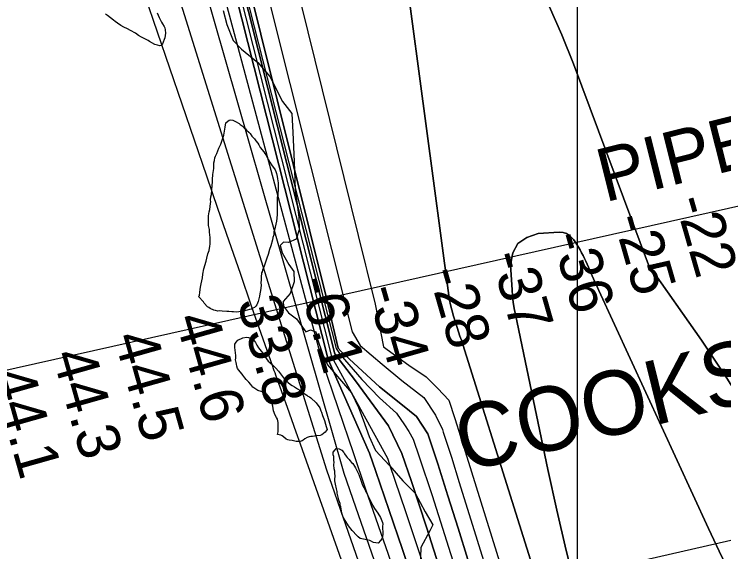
# Model space of a CAD drawing. Extents: x 3250478 to 3288318, y 788638 to 816472.
# Drawn here: x 3274716 to 3275823, y 796576 to 797415 of the extents above; entities that cross this region are included whole.
import ezdxf

# ---------------------------------------------------------------- set-up
doc = ezdxf.new("R2010")
doc.units = 0
for name, color, linetype in [('V-GRID-MAJR', 7, 'Continuous'), ('V-RIVR-EDGE', 7, 'Continuous'), ('V-RIVR-RANG', 7, 'Continuous'), ('V-SITE-VEGE', 7, 'Continuous'), ('V-TOPO-DPTH', 7, 'Continuous'), ('V-TOPO-GNAM-IDEN', 7, 'Continuous'), ('V-TOPO-MAJR', 7, 'Continuous'), ('V-TOPO-MINR', 7, 'Continuous'), ('V-TOPO-WATR', 7, 'Continuous'), ('V-UTIL-IDEN', 7, 'Continuous'), ('V-UTIL-LINE', 7, 'Continuous')]:
    doc.layers.add(name, color=color, linetype=linetype)

msp = doc.modelspace()

# ---------------------------------------------------------------- linework, layer by layer
at = {"layer": 'V-GRID-MAJR'}
msp.add_spline([(3275593.9, 794016.6), (3275594.8, 800075.6), (3275595.7, 806137.8), (3275596.6, 812200), (3275596.6, 812203)], degree=3, dxfattribs=at)
at = {"layer": 'V-RIVR-EDGE'}
msp.add_lwpolyline([(3275041.6, 797420.6), (3275047.7, 797398.4), (3275057.2, 797373.6), (3275070.6, 797360.1), (3275095.8, 797339.1), (3275114.8, 797317.4), (3275134.3, 797278.6), (3275149, 797259.5), (3275150.3, 797229.9), (3275152.3, 797184.7), (3275154, 797141.2), (3275159.9, 797097.7), (3275160.3, 797078.2), (3275155.5, 797063.8), (3275143.7, 797058.2), (3275135.9, 797058.7), (3275130.7, 797053.9), (3275133.7, 797042.2), (3275144.1, 797023.9), (3275151.9, 797013), (3275152.7, 796996.9), (3275146.2, 796978.7), (3275135.3, 796966.5), (3275136.1, 796959.1), (3275143.9, 796948.7), (3275156.1, 796939.1), (3275170.8, 796919.1), (3275177.8, 796922.1), (3275186.4, 796919), (3275187.7, 796910.8), (3275197.2, 796882.9), (3275204.6, 796867.7), (3275241.8, 796823.7), (3275252.7, 796801.1), (3275260, 796781.5), (3275269.5, 796755.4), (3275279.4, 796734), (3275301.1, 796710.5), (3275321.9, 796686.6), (3275341.4, 796667.4), (3275357, 796638.2), (3275368.7, 796617.8), (3275364.3, 796608.6), (3275350.3, 796582.2), (3275349, 796551.7)], dxfattribs=at)
at = {"layer": 'V-SITE-VEGE'}
for points in [[(3274938.9, 797416.7), (3274941.8, 797409.7), (3274943.5, 797406.4), (3274945.4, 797402.2), (3274947, 797399.8), (3274949.9, 797395.6), (3274950.9, 797393.2), (3274951.3, 797390.4), (3274951.8, 797384.9), (3274951.6, 797381.6), (3274950.8, 797377.9), (3274947.1, 797368.3), (3274945.3, 797365.8), (3274943.2, 797365.1), (3274939.2, 797366.2), (3274935.2, 797367.6), (3274926.8, 797372), (3274924.6, 797373.4), (3274914.3, 797378.9), (3274910, 797381.5), (3274905, 797384.8), (3274897.2, 797389.4), (3274892.8, 797391.7), (3274886.9, 797394.3), (3274882.3, 797396.9), (3274877, 797400.4), (3274873.5, 797403.1), (3274870.7, 797405.5), (3274861.6, 797412.8), (3274858.5, 797414.9)], [(3275011.2, 796965.7), (3275003.3, 796974), (3275005, 796975.9), (3275005.2, 796980.8), (3275006.5, 796988.5), (3275007.6, 796994), (3275009.4, 797003), (3275010.2, 797009.1), (3275011.8, 797017.1), (3275015.4, 797029.5), (3275016.5, 797033.8), (3275018.1, 797040.9), (3275019.8, 797045.8), (3275021.1, 797052.9), (3275021.6, 797055.7), (3275021.7, 797063), (3275021.6, 797066.7), (3275020.9, 797069.7), (3275020.4, 797074.9), (3275020.3, 797078.9), (3275019.2, 797085), (3275019.1, 797089.2), (3275018.9, 797096), (3275018.7, 797100.2), (3275019.8, 797106.4), (3275020.9, 797110.1), (3275022.2, 797119), (3275022.4, 797121.8), (3275022, 797124.8), (3275022.8, 797129.4), (3275023.6, 797133.4), (3275024.3, 797140.5), (3275025.1, 797153.4), (3275025, 797156.7), (3275025.7, 797164.4), (3275027.2, 797173.9), (3275027.1, 797178.2), (3275027.3, 797182.5), (3275028.1, 797186.5), (3275028.6, 797190.5), (3275029.7, 797193.3), (3275031.7, 797197.3), (3275035.2, 797205.4), (3275038, 797211.9), (3275043.1, 797226.1), (3275045.2, 797238.1), (3275046.2, 797245.2), (3275048.9, 797247.7), (3275051.3, 797249.3), (3275054, 797250), (3275056.8, 797249.5), (3275060.9, 797247.2), (3275066.8, 797244.3), (3275068.3, 797242.5), (3275071.2, 797240.4), (3275074.6, 797237.5), (3275076.5, 797236), (3275078.4, 797233.6), (3275081.6, 797230.3), (3275083.8, 797228.3), (3275086.6, 797224.4), (3275088.5, 797222), (3275090.7, 797219.9), (3275093, 797217.2), (3275095.8, 797213.3), (3275097.4, 797210.6), (3275099.7, 797206.4), (3275105.1, 797199.8), (3275107, 797197.1), (3275108.3, 797195), (3275109.9, 797192), (3275112.2, 797188.4), (3275114.5, 797183.6), (3275117, 797179.7), (3275118.3, 797177.9), (3275120.5, 797175.2), (3275123.1, 797171.6), (3275124.1, 797169.2), (3275125.1, 797165.9), (3275126.1, 797161.6), (3275126.6, 797157.6), (3275127.7, 797151.6), (3275127.8, 797146.7), (3275127.7, 797139.9), (3275127.2, 797135.6), (3275127, 797132), (3275126.2, 797128.6), (3275126.1, 797122.7), (3275126.2, 797118.5), (3275126.1, 797111.1), (3275126.3, 797106.5), (3275126.1, 797101.9), (3275125.7, 797096.1), (3275125.2, 797091.8), (3275121.9, 797077.6), (3275121.1, 797074.9), (3275120.6, 797070.3), (3275119.2, 797066.2), (3275119, 797062.3), (3275116.2, 797053), (3275114.3, 797047.4)], [(3275114.3, 797047.4), (3275111.8, 797039.4), (3275109.8, 797033.8), (3275105.9, 797021.5), (3275104.7, 797018.7), (3275103, 797015), (3275102.5, 797012.8), (3275101.6, 797010.9), (3275101.2, 797004.2), (3275101.3, 797000.2), (3275100.8, 796995.3), (3275100.9, 796992), (3275100.5, 796987.3), (3275100.3, 796983.7), (3275099.2, 796978.4), (3275098.7, 796974.7), (3275096.2, 796966.1), (3275094.2, 796961.2), (3275092.7, 796959), (3275090.7, 796957.1), (3275088.2, 796956.1), (3275086.2, 796954.5), (3275082.8, 796953.8), (3275075.8, 796951.7), (3275072.5, 796951.1), (3275070.4, 796950.6), (3275066.1, 796950.2), (3275062.7, 796949.8), (3275058.1, 796950), (3275055.1, 796950.2), (3275050.8, 796950.7), (3275047.7, 796950.6), (3275040.1, 796951), (3275036.1, 796951.5), (3275033.3, 796951.4), (3275029.9, 796952.5), (3275027.1, 796953), (3275021.6, 796955.6), (3275019.7, 796956.8), (3275017.5, 796957.9), (3275012.1, 796963.9), (3275011.2, 796965.7)], [(3275060.1, 796894.6), (3275060, 796899.5), (3275062, 796903), (3275064.7, 796905.8), (3275066.8, 796907.1), (3275070.4, 796908.7), (3275072.5, 796909.4), (3275078.3, 796910.5), (3275081.4, 796910), (3275086.6, 796908.6), (3275088.5, 796907.1), (3275090.7, 796904.4), (3275092, 796902.3), (3275094.3, 796898.4), (3275097.1, 796894.2), (3275101.3, 796888.8), (3275103.5, 796885.5), (3275106.7, 796880.4), (3275112.1, 796873.3), (3275114.7, 796871.2), (3275118.8, 796867.3), (3275121.3, 796864.7), (3275124.1, 796862.3), (3275128.2, 796857.5), (3275132.7, 796851.2), (3275135.9, 796847), (3275142.5, 796840.2), (3275146.9, 796836.7), (3275149.4, 796835.2), (3275153.1, 796833.2), (3275157.8, 796830), (3275161.5, 796827.9), (3275165, 796825.3), (3275168.4, 796822.9), (3275172.5, 796820), (3275174.1, 796818.5), (3275176.5, 796817.4), (3275178.4, 796816.2), (3275186.9, 796808.2), (3275192.7, 796800.4), (3275194.3, 796795.9), (3275195.3, 796793.4), (3275197, 796788.6), (3275200, 796780.4), (3275201.4, 796775), (3275202.7, 796771.3), (3275204.1, 796766.8), (3275201.1, 796762.4), (3275198.5, 796760.2), (3275195.8, 796758.3), (3275193, 796757), (3275187.2, 796756.5), (3275181.2, 796755.7), (3275178.7, 796755.6), (3275175.7, 796754.9), (3275172.6, 796753.9), (3275169.3, 796752), (3275166.6, 796750.1), (3275164.8, 796749.1), (3275161.8, 796747.8), (3275155.7, 796747.6), (3275149.5, 796749.5), (3275144.9, 796750), (3275142.8, 796750.6), (3275140.3, 796751.7), (3275135.9, 796754.9), (3275133.7, 796756.7), (3275131.8, 796757.9), (3275126.6, 796758.9), (3275127.7, 796762.7), (3275127.8, 796771.2), (3275127.6, 796777.6), (3275126.5, 796782.5), (3275125.2, 796785.5), (3275122.9, 796789.1), (3275120.3, 796795.5), (3275119.5, 796802.8), (3275118.4, 796806.7), (3275116.1, 796812.8), (3275114.5, 796815.8), (3275111.6, 796819.7), (3275109.7, 796821.5), (3275106.3, 796823.5), (3275104.1, 796824.7), (3275101, 796826.1), (3275096.1, 796827.2), (3275088.3, 796832.5), (3275084.8, 796836.9), (3275081.9, 796840.5), (3275077.8, 796844.7), (3275075.6, 796847.4), (3275072.7, 796851.3), (3275071.4, 796853.1), (3275068.3, 796856.6), (3275066.4, 796859), (3275064.4, 796862), (3275063.1, 796865.4), (3275062.7, 796868.7), (3275062, 796871.1)], [(3275062, 796871.1), (3275061.3, 796875.1), (3275061.5, 796877.9), (3275061.7, 796882.2), (3275060.1, 796894.6)]]:
    msp.add_lwpolyline(points, dxfattribs=at)
msp.add_lwpolyline([(3275255.7, 796596.7), (3275252.6, 796599), (3275250.4, 796601.1), (3275242.8, 796608.8), (3275237.4, 796616), (3275230.3, 796627.1), (3275227.4, 796633.2), (3275226.3, 796639.2), (3275225.9, 796642.6), (3275225.1, 796645.9), (3275224.5, 796648.4), (3275224.1, 796651.1), (3275222.4, 796656.3), (3275221, 796661.1), (3275219.6, 796667.2), (3275219.8, 796669.7), (3275218.5, 796674.2), (3275217, 796681.5), (3275216, 796686.4), (3275215.9, 796689.4), (3275216.4, 796693.4), (3275216.2, 796699.2), (3275215.8, 796701.7), (3275215.1, 796705.3), (3275214.6, 796711.7), (3275214.8, 796715.7), (3275214.4, 796718.4), (3275214.6, 796720.9), (3275214.2, 796724.3), (3275213.5, 796727.3), (3275213.4, 796731), (3275216.3, 796735), (3275218.1, 796736.9), (3275223, 796736.5), (3275226.8, 796734.4), (3275230.2, 796730.9), (3275231.2, 796728.7), (3275233.5, 796725.1), (3275235.4, 796722.7), (3275238.2, 796719.8), (3275239.5, 796718), (3275242, 796715.3), (3275243.9, 796713.5), (3275246.5, 796709.3), (3275248.1, 796706.9), (3275249.4, 796704.8), (3275253.3, 796696.1), (3275257, 796685.8), (3275259.3, 796679.7), (3275261, 796676.1), (3275262.6, 796673.4), (3275264.2, 796669.1), (3275265.8, 796667.1), (3275269.7, 796658.9), (3275271.4, 796655.3), (3275274.6, 796648.7), (3275277.8, 796643.5), (3275283, 796636), (3275287.1, 796629.1), (3275290.4, 796621.3), (3275290.8, 796618.8), (3275290.3, 796615.8), (3275290.7, 796603.2), (3275290.5, 796599.6), (3275289.4, 796595.9), (3275287.3, 796593.6), (3275283.8, 796589), (3275280.1, 796589.5), (3275276.4, 796590.3), (3275270.5, 796593.5), (3275265.8, 796594.5), (3275263.1, 796595.1)], close=True, dxfattribs=at)
at = {"layer": 'V-TOPO-DPTH'}
for points in [[(3275320.7, 796729.2), (3275299.6, 796772.4), (3275248, 796842.5), (3275216.1, 796884.8), (3275081.1, 797418.9), (3275012.4, 797685.4), (3274892, 798494.3), (3274803.2, 799219.5)], [(3274803.2, 799219.5), (3274892, 798494.3), (3275012.4, 797685.4), (3275081.1, 797418.9), (3275216.1, 796884.8), (3275248, 796842.5), (3275299.6, 796772.4), (3275320.7, 796729.2)], [(3275360.9, 796759.7), (3275343.1, 796787), (3275321.3, 796804.6), (3275285.9, 796832.9), (3275225.3, 796888.9), (3275221.2, 796893.6), (3275201.7, 796975.5), (3275024.8, 797689.1), (3274903.6, 798500.7), (3274917.8, 799176.2)], [(3274917.8, 799176.2), (3274903.6, 798500.7), (3275024.8, 797689.1), (3275201.7, 796975.5), (3275221.2, 796893.6), (3275225.3, 796888.9), (3275285.9, 796832.9), (3275321.3, 796804.6), (3275343.1, 796787), (3275360.9, 796759.7)], [(3275270.1, 796729.6), (3275205.7, 796875.8), (3275003.6, 797674.8), (3274861.6, 798489.6), (3274742.1, 799152.7)], [(3275581, 796372.7), (3275415.4, 796899.2), (3275413.3, 796905.8), (3275411.1, 796912.4), (3275409, 796918.9), (3275406.8, 796925.5), (3275404.7, 796932), (3275402.6, 796938.6), (3275400.7, 796945.2), (3275398.9, 796951.9), (3275398.5, 796953.4), (3275396.6, 796960.9), (3275395, 796968.4), (3275393.7, 796975.9), (3275392.5, 796983.5), (3275291.2, 797742.6)], [(3275291.2, 797742.6), (3275392.5, 796983.5), (3275393.7, 796975.9), (3275395, 796968.4), (3275396.6, 796960.9), (3275398.5, 796953.4), (3275398.9, 796951.9), (3275400.7, 796945.2), (3275402.6, 796938.6), (3275404.7, 796932), (3275406.8, 796925.5), (3275409, 796918.9), (3275411.1, 796912.4), (3275413.3, 796905.8), (3275415.4, 796899.2), (3275581, 796372.7)], [(3275095.1, 797707.7), (3275263.8, 797023), (3275266.1, 797014.8), (3275279, 796962.4), (3275291.7, 796895.7), (3275331.3, 796866.8), (3275358.4, 796848.7), (3275376.4, 796830.7), (3275393.8, 796812.3), (3275402.9, 796783.9), (3275411.9, 796755.5), (3275524.5, 796394.5), (3275539, 796348.1), (3275553.5, 796301.6), (3275568, 796255.2), (3275582.5, 796208.8), (3275596.8, 796162.4), (3275610.6, 796115.8), (3275623.9, 796069)], [(3275095.1, 797707.7), (3275263.8, 797023), (3275266.1, 797014.8), (3275279, 796962.4), (3275291.7, 796895.7), (3275331.3, 796866.8), (3275358.4, 796848.7), (3275376.4, 796830.7), (3275393.8, 796812.3), (3275402.9, 796783.9), (3275411.9, 796755.5), (3275524.5, 796394.5), (3275539, 796348.1), (3275553.5, 796301.6), (3275568, 796255.2), (3275582.5, 796208.8), (3275596.8, 796162.4), (3275610.6, 796115.8), (3275623.9, 796069)], [(3275550.2, 797427.3), (3275569.9, 797382.5), (3275588.1, 797337.1), (3275705.3, 797023.3), (3275787.7, 796906), (3275827.6, 796846.5), (3275865.7, 796786), (3275901.1, 796723.9), (3275934.7, 796660.7), (3276015.3, 796501), (3276029.6, 796471.9), (3276043.3, 796442.5), (3276056.2, 796412.8), (3276068.7, 796382.8), (3276080.4, 796352.5), (3276091.7, 796322.1), (3276102.5, 796291.5), (3276112.8, 796260.7), (3276249.8, 795838.1)], [(3276249.8, 795838.1), (3276112.8, 796260.7), (3276102.5, 796291.5), (3276091.7, 796322.1), (3276080.4, 796352.5), (3276068.7, 796382.8), (3276056.2, 796412.8), (3276043.3, 796442.5), (3276029.6, 796471.9), (3276015.3, 796501), (3275934.7, 796660.7), (3275901.1, 796723.9), (3275865.7, 796786), (3275827.6, 796846.5), (3275787.7, 796906), (3275705.3, 797023.3), (3275588.1, 797337.1), (3275569.9, 797382.5), (3275550.2, 797427.3)], [(3275593, 796515.2), (3275576.8, 796577.9), (3275562, 796640.9), (3275548.1, 796704.2), (3275497.5, 796946), (3275495.8, 796955.6), (3275494.3, 796965.3), (3275493.2, 796975), (3275492.4, 796984.7), (3275490.1, 797023.6), (3275493.8, 797042), (3275501.5, 797056.8), (3275515.2, 797066.3), (3275533, 797072.3), (3275566, 797074.5), (3275571.9, 797074), (3275577.3, 797072.5), (3275582, 797069.4), (3275586.3, 797065.4), (3275588, 797063.2), (3275590.9, 797059.2), (3275593.6, 797055.1), (3275596.2, 797051), (3275598.6, 797046.7), (3275600.9, 797042.3), (3275603.2, 797037.9), (3275605.3, 797033.5), (3275607.3, 797029), (3275611.4, 797019.8), (3275615.4, 797010.8), (3275619.5, 797001.7), (3275623.6, 796992.7), (3275627.7, 796983.7), (3275799, 796612), (3275815.6, 796576.5), (3275832.3, 796541)], [(3275832.3, 796541), (3275815.6, 796576.5), (3275799, 796612), (3275627.7, 796983.7), (3275623.6, 796992.7), (3275619.5, 797001.7), (3275615.4, 797010.8), (3275611.4, 797019.8), (3275607.3, 797029), (3275605.3, 797033.5), (3275603.2, 797037.9), (3275600.9, 797042.3), (3275598.6, 797046.7), (3275596.2, 797051), (3275593.6, 797055.1), (3275590.9, 797059.2), (3275588, 797063.2), (3275586.3, 797065.4), (3275582, 797069.4), (3275577.3, 797072.5), (3275571.9, 797074), (3275566, 797074.5), (3275533, 797072.3), (3275515.2, 797066.3), (3275501.5, 797056.8), (3275493.8, 797042), (3275490.1, 797023.6), (3275492.4, 796984.7), (3275493.2, 796975), (3275494.3, 796965.3), (3275495.8, 796955.6), (3275497.5, 796946), (3275548.1, 796704.2), (3275562, 796640.9), (3275576.8, 796577.9), (3275593, 796515.2)], [(3275584.7, 796030.7), (3275566.2, 796095.3), (3275547.2, 796159.9), (3275527.7, 796224.2), (3275508.2, 796288.6), (3275488.5, 796352.9), (3275468.7, 796417.2), (3275408.2, 796612.7), (3275392.4, 796662.9), (3275376.4, 796712.9), (3275360.9, 796759.7)], [(3275360.9, 796759.7), (3275376.4, 796712.9), (3275392.4, 796662.9), (3275408.2, 796612.7), (3275468.7, 796417.2), (3275488.5, 796352.9), (3275508.2, 796288.6), (3275527.7, 796224.2), (3275547.2, 796159.9), (3275566.2, 796095.3), (3275584.7, 796030.7)], [(3275499.9, 795975.4), (3275455.3, 796136.6), (3275437.6, 796199.9), (3275419.5, 796263.1), (3275401, 796326.2), (3275382.2, 796389.2), (3275381.9, 796390), (3275362.3, 796453.2), (3275342.3, 796516.3), (3275321.5, 796579.1), (3275300.3, 796641.8), (3275279.8, 796701.1), (3275270.1, 796729.6)], [(3275536.6, 796022.8), (3275514.3, 796101.6), (3275511.9, 796110.1), (3275487.7, 796192.9), (3275463.3, 796275.7), (3275438.5, 796358.4), (3275413.4, 796441), (3275404.3, 796470.9), (3275381.9, 796542.6), (3275359.1, 796614.2), (3275335.5, 796685.5), (3275320.7, 796729.2)], [(3275320.7, 796729.2), (3275335.5, 796685.5), (3275359.1, 796614.2), (3275381.9, 796542.6), (3275404.3, 796470.9), (3275413.4, 796441), (3275438.5, 796358.4), (3275463.3, 796275.7), (3275487.7, 796192.9), (3275511.9, 796110.1), (3275514.3, 796101.6), (3275536.6, 796022.8)]]:
    msp.add_lwpolyline(points, dxfattribs=at)
at = {"layer": 'V-TOPO-MAJR'}
for points in [[(3274650.9, 799170.7), (3274703.8, 798821.2), (3274763.8, 798489.6), (3274905.8, 797655.9), (3275202.8, 796703.7)], [(3275202.8, 796703.7), (3275232.4, 796618.4), (3275296.9, 796433.3), (3275307.5, 796402.2), (3275317.9, 796370.9), (3275327.8, 796339.5), (3275337.4, 796308.1), (3275337.7, 796307), (3275346.8, 796276), (3275355.6, 796244.8), (3275364.1, 796213.5), (3275372.3, 796182.2), (3275475.9, 795779.8)]]:
    msp.add_lwpolyline(points, dxfattribs=at)
at = {"layer": 'V-TOPO-MINR'}
for points in [[(3274856, 799209.7), (3274898.3, 798500), (3275016.3, 797685.3), (3275218.2, 796893), (3275224.1, 796883.6), (3275258.3, 796844.7), (3275285.9, 796815.8), (3275312.4, 796792.3), (3275324.8, 796774), (3275331.3, 796763.4), (3275338.4, 796751.6)], [(3275036.8, 799181.6), (3274976.4, 798758.3), (3274948.6, 798615), (3274936.2, 798528.3), (3274935.2, 798494.3), (3274940.4, 798448.9), (3275048.6, 797694.4), (3275243, 796919.1), (3275255.6, 796897.5), (3275289.9, 796868.6), (3275320.5, 796843.3), (3275354.8, 796816.3), (3275372.8, 796789.2), (3275383.7, 796766.6)], [(3275360.9, 796759.7), (3275343.1, 796787), (3275321.3, 796804.6), (3275285.9, 796832.9), (3275225.3, 796888.9), (3275221.2, 796893.6), (3275201.7, 796975.5), (3275024.8, 797689.1), (3274903.6, 798500.7), (3274917.8, 799176.2)], [(3274775.8, 799159.5), (3274883.7, 798486.4), (3275010, 797674.9), (3275210.9, 796880.7), (3275298.1, 796721.6)], [(3274678, 799145.7), (3274792.2, 798464.3), (3274953.1, 797665.3), (3275230, 796698.5)], [(3274706.5, 799151.5), (3274830, 798470.6), (3274984.7, 797662.2), (3275196.2, 796872.7), (3275244.9, 796729.1)], [(3274742.1, 799152.7), (3274861.6, 798489.6), (3275003.6, 797674.8), (3275205.7, 796875.8), (3275270.1, 796729.6)], [(3275291.2, 797742.6), (3275392.5, 796983.5), (3275393.7, 796975.9), (3275395, 796968.4), (3275396.6, 796960.9), (3275398.5, 796953.4), (3275398.9, 796951.9), (3275400.7, 796945.2), (3275402.6, 796938.6), (3275404.7, 796932), (3275406.8, 796925.5), (3275409, 796918.9), (3275411.1, 796912.4), (3275413.3, 796905.8), (3275415.4, 796899.2), (3275581, 796372.7)], [(3275095.1, 797707.7), (3275263.8, 797023), (3275266.1, 797014.8), (3275279, 796962.4), (3275291.7, 796895.7), (3275331.3, 796866.8), (3275358.4, 796848.7), (3275376.4, 796830.7), (3275393.8, 796812.3), (3275402.9, 796783.9), (3275411.9, 796755.5), (3275524.5, 796394.5), (3275539, 796348.1), (3275553.5, 796301.6), (3275568, 796255.2), (3275582.5, 796208.8), (3275596.8, 796162.4), (3275610.6, 796115.8), (3275623.9, 796069)], [(3274881.3, 797556.4), (3275015.7, 797162.4), (3275033.1, 797111.7), (3275050.5, 797061), (3275068.1, 797010.4), (3275085.7, 796959.7), (3275118.7, 796865.2), (3275119.9, 796861.9), (3275121.1, 796858.6), (3275122.2, 796855.3), (3275123.4, 796852), (3275134.7, 796820.4), (3275141.5, 796801.3), (3275148.3, 796782.2), (3275155.1, 796763.1), (3275161.8, 796744), (3275295.8, 796364.3)], [(3276249.8, 795838.1), (3276112.8, 796260.7), (3276102.5, 796291.5), (3276091.7, 796322.1), (3276080.4, 796352.5), (3276068.7, 796382.8), (3276056.2, 796412.8), (3276043.3, 796442.5), (3276029.6, 796471.9), (3276015.3, 796501), (3275934.7, 796660.7), (3275901.1, 796723.9), (3275865.7, 796786), (3275827.6, 796846.5), (3275787.7, 796906), (3275705.3, 797023.3), (3275588.1, 797337.1), (3275569.9, 797382.5), (3275550.2, 797427.3)], [(3275832.3, 796541), (3275815.6, 796576.5), (3275799, 796612), (3275627.7, 796983.7), (3275623.6, 796992.7), (3275619.5, 797001.7), (3275615.4, 797010.8), (3275611.4, 797019.8), (3275607.3, 797029), (3275605.3, 797033.5), (3275603.2, 797037.9), (3275600.9, 797042.3), (3275598.6, 797046.7), (3275596.2, 797051), (3275593.6, 797055.1), (3275590.9, 797059.2), (3275588, 797063.2), (3275586.3, 797065.4), (3275582, 797069.4), (3275577.3, 797072.5), (3275571.9, 797074), (3275566, 797074.5), (3275533, 797072.3), (3275515.2, 797066.3), (3275501.5, 797056.8), (3275493.8, 797042), (3275490.1, 797023.6), (3275492.4, 796984.7), (3275493.2, 796975), (3275494.3, 796965.3), (3275495.8, 796955.6), (3275497.5, 796946), (3275548.1, 796704.2), (3275562, 796640.9), (3275576.8, 796577.9), (3275593, 796515.2)], [(3275383.7, 796766.6), (3275385.1, 796762.5), (3275397.7, 796723.3), (3275410, 796684), (3275496.5, 796405.7), (3275513.7, 796350.4), (3275530.8, 796295.1), (3275547.8, 796239.8), (3275564.9, 796184.4), (3275581.5, 796129), (3275597.7, 796073.4)], [(3275360.9, 796759.7), (3275376.4, 796712.9), (3275392.4, 796662.9), (3275408.2, 796612.7), (3275468.7, 796417.2), (3275488.5, 796352.9), (3275508.2, 796288.6), (3275527.7, 796224.2), (3275547.2, 796159.9), (3275566.2, 796095.3), (3275584.7, 796030.7)], [(3275338.4, 796751.6), (3275347.7, 796724.1), (3275367.7, 796663.5), (3275387.2, 796602.6), (3275406.3, 796541.7), (3275441, 796429), (3275463.4, 796355.6), (3275485.7, 796282.2), (3275507.7, 796208.6), (3275529.5, 796135.1), (3275550.8, 796061.4)], [(3275244.9, 796729.1), (3275263.9, 796673.5), (3275299.1, 796572), (3275316.8, 796519.9), (3275334.1, 796467.7), (3275350.7, 796415.2), (3275367, 796362.6), (3275367.3, 796361.6), (3275382.8, 796309.3), (3275398, 796257), (3275412.7, 796204.5), (3275427.2, 796151.9), (3275492.2, 795911)], [(3275270.1, 796729.6), (3275279.8, 796701.1), (3275300.3, 796641.8), (3275321.5, 796579.1), (3275342.3, 796516.3), (3275362.3, 796453.2), (3275381.9, 796390), (3275382.2, 796389.2), (3275401, 796326.2), (3275419.5, 796263.1), (3275437.6, 796199.9), (3275455.3, 796136.6), (3275499.9, 795975.4)], [(3275298.1, 796721.6), (3275301.5, 796711.8), (3275326.3, 796638.5), (3275350.5, 796565.1), (3275374, 796491.4), (3275397, 796417.6), (3275397.1, 796417.1), (3275419.4, 796343.3), (3275441.3, 796269.4), (3275462.8, 796195.4), (3275484, 796121.3), (3275507.2, 796038.9)], [(3275230, 796698.5), (3275248.1, 796645.9), (3275298, 796502.6), (3275312.2, 796460.9), (3275326, 796419.2), (3275339.2, 796377.3), (3275352.1, 796335.3), (3275352.4, 796334.2), (3275364.7, 796292.6), (3275376.7, 796250.8), (3275388.2, 796209), (3275399.5, 796167.1), (3275484.2, 795845.9)]]:
    msp.add_lwpolyline(points, dxfattribs=at)
at = {"layer": 'V-TOPO-WATR'}
for points in [[(3275320.7, 796729.2), (3275299.6, 796772.4), (3275248, 796842.5), (3275216.1, 796884.8), (3275081.1, 797418.9), (3275012.4, 797685.4), (3274892, 798494.3), (3274803.2, 799219.5)], [(3275320.7, 796729.2), (3275335.5, 796685.5), (3275359.1, 796614.2), (3275381.9, 796542.6), (3275404.3, 796470.9), (3275413.4, 796441), (3275438.5, 796358.4), (3275463.3, 796275.7), (3275487.7, 796192.9), (3275511.9, 796110.1), (3275514.3, 796101.6), (3275536.6, 796022.8)]]:
    msp.add_lwpolyline(points, dxfattribs=at)
at = {"layer": 'V-UTIL-LINE'}
for points in [[(3274180.3, 796742), (3278434.3, 797696.7), (3279181.3, 797847.9), (3280704.9, 797706.3), (3281577.3, 797678.6)], [(3281615.2, 797623.2), (3280692.5, 797638.3), (3280463.2, 797631.9), (3278519.4, 797207.6), (3274234.6, 796227.9)]]:
    msp.add_lwpolyline(points, dxfattribs=at)

# ---------------------------------------------------------------- texts
at = {"layer": 'V-RIVR-RANG'}
for s, rotation, p in [('-22', 286.0608, (3275745.5, 797124.1)), ('-25', 286.0608, (3275649.6, 797095.6)), ('-36', 286.0608, (3275553.7, 797067.2)), ('-37', 286.0608, (3275458.2, 797037.5)), ('-28', 286.0608, (3275361.4, 797012.3)), ('-6.1', 285.7783, (3275157.9, 796998.6)), ('-34', 286.0608, (3275265.3, 796984.7)), ('33.8', 285.7783, (3275063.3, 796965.6)), ('44.6', 285.7783, (3274966.6, 796940)), ('44.5', 285.7783, (3274871, 796910.7)), ('44.3', 285.7783, (3274774.8, 796883.3)), ('44.1', 285.7783, (3274679.3, 796853.6))]:
    msp.add_text(s, height=67, rotation=rotation, dxfattribs=at).set_placement(p)
at = {"layer": 'V-TOPO-GNAM-IDEN'}
msp.add_text('COOKS LDG.', height=100, rotation=13.812, dxfattribs=at).set_placement((3275417.7, 796699.7))
at = {"layer": 'V-UTIL-IDEN'}
msp.add_text('PIPELINE CO.', height=83, rotation=14.0859, dxfattribs=at).set_placement((3275637.1, 797120.9))

doc.saveas('drawing.dxf')
